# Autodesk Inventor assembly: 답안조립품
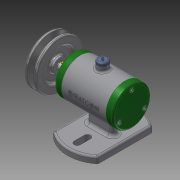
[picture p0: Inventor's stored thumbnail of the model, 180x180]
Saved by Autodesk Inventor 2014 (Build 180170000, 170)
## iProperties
Created: 2017-12
Part Number: 답안조립품
Document SubType Name: Assembly
Designer: 거성
Author: 거성
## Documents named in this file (11)
- C:\Users\거성\Desktop\471208V1027\답안조립품.iam
- C:\Users\거성\Desktop\471208V1027\본체.ipt
- C:\Users\거성\Desktop\471208V1027\앞커버.ipt
- C:\Users\거성\Desktop\471208V1027\오일 실 15 25 7.ipt
- C:\Users\거성\Desktop\471208V1027\베어링 15 x 32 x 9.ipt
- C:\Users\거성\Desktop\471208V1027\축.ipt
- C:\Users\거성\Desktop\471208V1027\뒤커버.ipt
- C:\Users\거성\Desktop\471208V1027\볼트 M4 x 12.ipt
- C:\Users\거성\Desktop\471208V1027\고무캡.ipt
- C:\Users\거성\Desktop\471208V1027\키 3 x 3 x 12.ipt
- C:\Users\거성\Desktop\471208V1027\V벨트풀리.ipt
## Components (2 placed, 2 different names)
1. 고무캡:1
2. V벨트풀리:1
